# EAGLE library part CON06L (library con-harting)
CONNECTOR
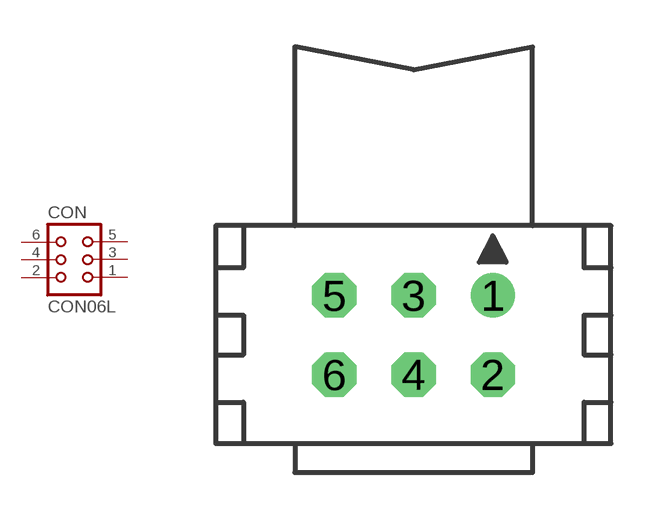
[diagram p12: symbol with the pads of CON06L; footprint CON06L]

Designator prefix CON

## CON06L (OC_FARNELL: unknown; OC_NEWARK: unknown)  [CON06L]
1  1  pas
2  2  pas
3  3  pas
4  4  pas
5  5  pas
6  6  pas

## Footprint CON06L (pad centres in mm)
CONNECTOR
drill 0.914 round: 1 2.54,1.27
drill 0.914 octagon: 2 2.54,-1.27; 3 0,1.27; 4 0,-1.27; 5 -2.54,1.27; 6 -2.54,-1.27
